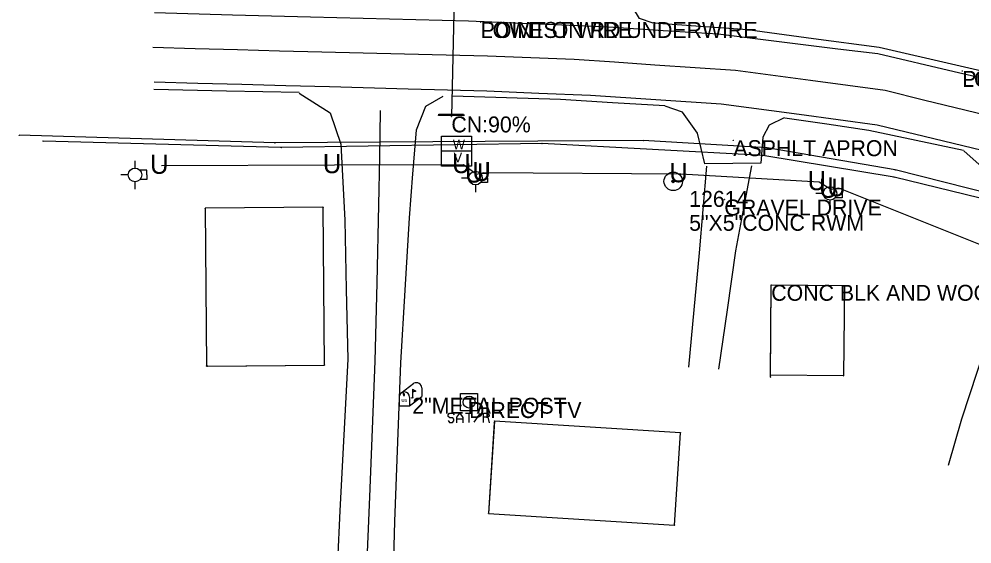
# Model space of a CAD drawing. Extents: x 1050807 to 1053552, y 395828 to 398415.
# Drawn here: x 1051514.4 to 1051813.5, y 397927.2 to 398091.9 of the extents above; entities that cross this region are included whole.
import ezdxf

# ---------------------------------------------------------------- set-up
doc = ezdxf.new("R2010")
doc.units = 0
for name, color, linetype in [('Default', 7, 'Continuous'), ('S_BUILDING', 7, 'Continuous'), ('S_BUILDING_ANNOT', 7, 'Continuous'), ('S_CROSS_DRAIN', 7, 'Continuous'), ('S_CROSS_DRAIN_ANNOT', 7, 'Continuous'), ('S_DRG_PT_SYM', 7, 'Continuous'), ('S_DRIVEWAY', 7, 'Continuous'), ('S_EDGE_PAVEMENT', 7, 'Continuous'), ('S_ELECTRIC_UTILITIES_ANNOT', 7, 'Continuous'), ('S_HEADWALL', 7, 'Continuous'), ('S_IRON_PIN', 7, 'Continuous'), ('S_IRON_PIN_ANNOT', 7, 'Continuous'), ('S_MAILBOX', 7, 'Continuous'), ('S_MAILBOX_ANNOT', 7, 'Continuous'), ('S_MSC_PT_SYM', 7, 'Continuous'), ('S_PAVEMENT_CROWN', 7, 'Continuous'), ('S_PHOTO_IRON_PIN', 7, 'Continuous'), ('S_SATELLITE_RECEIVER', 7, 'Continuous'), ('S_SATELLITE_RECEIVER_ANNOT', 7, 'Continuous'), ('S_SHOULDER', 7, 'Continuous'), ('S_STR_PT_SYM', 7, 'Continuous'), ('S_SURVEY_TEXT_ANNOT', 7, 'Continuous'), ('S_UNDERGROUND_CABLE', 7, 'Continuous'), ('S_UTILITY_POLE', 7, 'Continuous'), ('S_UTL_PT_SYM', 7, 'Continuous'), ('S_WATER_UTILITIES', 7, 'Continuous')]:
    doc.layers.add(name, color=color, linetype=linetype)

msp = doc.modelspace()

# ---------------------------------------------------------------- linework, layer by layer
at = {"layer": 'S_BUILDING'}
for p, q in [((1051609.83, 398032.84), (1051572.83, 398032.54)), ((1051572.83, 398032.54), (1051573.23, 397983.04)), ((1051610.23, 397983.34), (1051609.83, 398032.84)), ((1051750.22, 397979.55), (1051750.51, 398008.5)), ((1051750.22, 397980.2), (1051750.51, 398008.5)), ((1051750.51, 398008.5), (1051773.51, 398008.27)), ((1051773.51, 398008.27), (1051773.22, 397979.97)), ((1051573.23, 397983.04), (1051610.23, 397983.34)), ((1051573.61, 397983.04), (1051610.23, 397983.34)), ((1051773.22, 397979.97), (1051750.22, 397980.2)), ((1051663.58, 397965.75), (1051661.76, 397936.81)), ((1051663.55, 397965.29), (1051661.76, 397936.81)), ((1051721.97, 397962.09), (1051663.58, 397965.75)), ((1051720.15, 397933.14), (1051721.97, 397962.09)), ((1051661.76, 397936.81), (1051720.15, 397933.14))]:
    msp.add_line(p, q, dxfattribs=at)
at = {"layer": 'S_CROSS_DRAIN'}
msp.add_line((1051651.04, 398104.23), (1051650.09, 398061.31), dxfattribs=at)
at = {"layer": 'S_DRG_PT_SYM'}
msp.add_lwpolyline([(1051650.09, 398061.31), (1051650.09, 398061.36), (1051650.09, 398061.31), (1051650.04, 398061.31), (1051650.09, 398061.31), (1051650.09, 398061.26), (1051650.09, 398061.31), (1051650.14, 398061.31)], dxfattribs=at)
at = {"layer": 'S_DRIVEWAY'}
for points in [[(1051724.66, 397982.69), (1051726.32, 398000.62), (1051727.98, 398018.55), (1051729.11, 398032.13), (1051730.24, 398045.71)], [(1051744.33, 398045.87), (1051741.83, 398032.52), (1051739.33, 398019.18), (1051736.62, 398000.64), (1051733.9, 397982.1)], [(1051822.94, 398027.14), (1051824.81, 398010.97), (1051817.54, 397988.65), (1051810.28, 397966.32), (1051806.07, 397951.84)]]:
    msp.add_lwpolyline(points, dxfattribs=at)
at = {"layer": 'S_EDGE_PAVEMENT'}
for points in [[(1051713.48, 398090.6), (1051709.19, 398091.98), (1051705.31, 398098.47), (1051704.3, 398102.36), (1051704.31, 398113.47), (1051699.76, 398119.86), (1051701.99, 398138.89), (1051703.06, 398162.71)], [(1051831.93, 398069.76), (1051807.96, 398075.33), (1051783.99, 398080.9), (1051771.44, 398082.45), (1051758.89, 398083.99), (1051746.34, 398085.53), (1051733.79, 398087.07), (1051716.6, 398088.19), (1051699.41, 398089.32), (1051677.43, 398090.24), (1051655.45, 398091.16), (1051630.63, 398091.8), (1051605.81, 398092.43), (1051581.35, 398093.1), (1051556.88, 398093.77)], [(1051831.48, 398047.11), (1051807.63, 398052.86), (1051783.78, 398058.61), (1051759.29, 398061.91), (1051734.8, 398065.21), (1051714.29, 398066.53), (1051693.78, 398067.86), (1051677.51, 398068.56), (1051661.25, 398069.27), (1051636.55, 398069.92), (1051611.85, 398070.56), (1051598.08, 398070.93), (1051584.31, 398071.29), (1051570.54, 398071.66), (1051556.77, 398072.02)], [(1051602.35, 398068.65), (1051612.02, 398062.41), (1051615.42, 398052.6), (1051616.64, 398028.83), (1051617.09, 398007), (1051617.53, 397985.17), (1051616.73, 397969.32), (1051615.92, 397953.47), (1051615.11, 397937.61), (1051614.31, 397921.76), (1051613.72, 397908.61), (1051613.14, 397895.46), (1051612.55, 397882.3), (1051611.96, 397869.15), (1051612.02, 397847.38), (1051612.07, 397825.61), (1051611.81, 397807.62), (1051611.54, 397789.62)], [(1051647.36, 398067.62), (1051642.01, 398064.42), (1051639.06, 398057.05), (1051637.93, 398043.3), (1051636.8, 398029.54), (1051635.43, 398006.82), (1051634.07, 397984.09), (1051633.15, 397959.21), (1051632.23, 397934.32), (1051631.81, 397918.96), (1051631.38, 397903.6), (1051630.96, 397888.24), (1051630.54, 397872.88), (1051629.92, 397848.36), (1051629.3, 397823.83), (1051628.69, 397807.15), (1051628.08, 397790.46)], [(1051754.56, 398060.86), (1051749.82, 398058.53), (1051747.85, 398054.83), (1051747.28, 398046.63), (1051729.64, 398046.5), (1051727.32, 398056.1), (1051722.66, 398062.66), (1051717.25, 398064.51)], [(1051837.11, 398041.69), (1051834.35, 398039.68), (1051832.92, 398035.92), (1051829.91, 398026.23), (1051818.65, 398029.13), (1051819.81, 398036.54), (1051817.64, 398044.52), (1051811, 398050.54)]]:
    msp.add_lwpolyline(points, dxfattribs=at)
at = {"layer": 'S_HEADWALL'}
msp.add_lwpolyline([(1051653.95, 398061.96), (1051654.03, 398061.48), (1051646.07, 398061.59), (1051646.14, 398062.08), (1051653.87, 398062)], dxfattribs=at)
at = {"layer": 'S_IRON_PIN'}
for radius in [2.91, 0.411, 0.262, 0.212, 0.145, 0.0822, 0.0581]:
    msp.add_circle((1051719.74, 398040.95), radius, dxfattribs=at)
at = {"layer": 'S_MAILBOX'}
for p, q in [((1051634.21, 397974.51), (1051638.34, 397977.62)), ((1051637.83, 397975.8), (1051637.83, 397973.09)), ((1051640.78, 397976.15), (1051640.78, 397973.43)), ((1051633.66, 397973.24), (1051633.66, 397970.52)), ((1051636.98, 397970.52), (1051640.78, 397973.43)), ((1051636.98, 397973.24), (1051636.98, 397970.52)), ((1051633.66, 397970.52), (1051636.98, 397970.52))]:
    msp.add_line(p, q, dxfattribs=at)
for points in [[(1051634.84, 397974.35), (1051635.06, 397974.21), (1051635.06, 397973.83), (1051635.37, 397973.83), (1051635.37, 397974.19), (1051635.17, 397974.44), (1051634.84, 397974.38)], [(1051637.83, 397975.8), (1051638.93, 397975.14), (1051637.83, 397974.79)]]:
    msp.add_lwpolyline(points, dxfattribs=at)
for centre, end in [((1051639.11, 397976.15), 117.5718), ((1051635.32, 397973.24), 180)]:
    msp.add_arc(centre, 1.66, 0, end, dxfattribs=at)
msp.add_ellipse((1051637.83, 397973.09), major_axis=(0.145, 0.132), ratio=0.564646, dxfattribs=at)
at = {"layer": 'S_MSC_PT_SYM'}
for points in [[(1051659.3, 398090.93), (1051659.3, 398090.98), (1051659.3, 398090.93), (1051659.25, 398090.93), (1051659.3, 398090.93), (1051659.3, 398090.88), (1051659.3, 398090.93), (1051659.35, 398090.93)], [(1051810.46, 398075.58), (1051810.46, 398075.63), (1051810.46, 398075.58), (1051810.41, 398075.58), (1051810.46, 398075.58), (1051810.46, 398075.53), (1051810.46, 398075.58), (1051810.51, 398075.58)], [(1051738.6, 398053.86), (1051738.6, 398053.91), (1051738.6, 398053.86), (1051738.55, 398053.86), (1051738.6, 398053.86), (1051738.6, 398053.81), (1051738.6, 398053.86), (1051738.65, 398053.86)], [(1051735.78, 398035.25), (1051735.78, 398035.3), (1051735.78, 398035.25), (1051735.73, 398035.25), (1051735.78, 398035.25), (1051735.78, 398035.2), (1051735.78, 398035.25), (1051735.83, 398035.25)]]:
    msp.add_lwpolyline(points, dxfattribs=at)
at = {"layer": 'S_PAVEMENT_CROWN'}
for points in [[(1051823.74, 398060.25), (1051811.24, 398063.31), (1051798.75, 398066.36), (1051786.26, 398069.42), (1051762.78, 398072.58), (1051739.3, 398075.74), (1051726.62, 398076.59), (1051713.95, 398077.44), (1051701.28, 398078.29), (1051688.6, 398079.14), (1051675.02, 398079.7), (1051661.43, 398080.25), (1051648.42, 398080.55), (1051635.41, 398080.85), (1051622.4, 398081.15), (1051609.39, 398081.45), (1051596.15, 398081.82), (1051582.9, 398082.18), (1051569.66, 398082.54), (1051556.41, 398082.91)], [(1051619.24, 397791.01), (1051619.65, 397803.82), (1051620.06, 397816.63), (1051620.48, 397829.45), (1051620.89, 397842.26), (1051621.71, 397867.23), (1051622.53, 397892.19), (1051623.49, 397917.08), (1051624.46, 397941.96), (1051625.3, 397963.26), (1051626.14, 397984.55), (1051626.74, 398009.08), (1051627.35, 398033.62), (1051627.62, 398048.39), (1051627.88, 398063.17)]]:
    msp.add_lwpolyline(points, dxfattribs=at)
at = {"layer": 'S_PHOTO_IRON_PIN'}
msp.add_line((1051655.65, 397971.73), (1051655.65, 397971.73), dxfattribs=at)
at = {"layer": 'S_SATELLITE_RECEIVER'}
for p, q in [((1051649.04, 397967.75), (1051649.5, 397968.21)), ((1051649.04, 397967.2), (1051649.04, 397967.75)), ((1051649.58, 397966.82), (1051649.04, 397967.2)), ((1051649.04, 397965.96), (1051649.5, 397965.34)), ((1051649.5, 397968.21), (1051650.51, 397968.21)), ((1051649.5, 397965.34), (1051650.43, 397965.34)), ((1051650.51, 397966.82), (1051649.58, 397966.82)), ((1051650.43, 397965.34), (1051650.9, 397965.89)), ((1051650.51, 397968.21), (1051650.97, 397967.75)), ((1051650.9, 397966.35), (1051650.51, 397966.82)), ((1051650.9, 397965.89), (1051650.9, 397966.35)), ((1051651.75, 397966.97), (1051652.76, 397968.21)), ((1051651.75, 397965.19), (1051651.75, 397966.97)), ((1051653.61, 397966.35), (1051651.75, 397966.35)), ((1051652.76, 397968.21), (1051653.69, 397966.89)), ((1051653.69, 397966.89), (1051653.69, 397965.19)), ((1051654.54, 397968.21), (1051656.48, 397968.21)), ((1051655.55, 397968.21), (1051655.55, 397965.34)), ((1051657.25, 397965.42), (1051659.19, 397968.21)), ((1051660.2, 397965.34), (1051660.2, 397968.21)), ((1051660.2, 397968.21), (1051661.44, 397968.21)), ((1051661.51, 397966.97), (1051660.2, 397966.97)), ((1051661.44, 397968.21), (1051661.9, 397967.75)), ((1051661.9, 397967.36), (1051661.51, 397966.97)), ((1051661.51, 397966.97), (1051661.9, 397965.27)), ((1051661.9, 397967.75), (1051661.9, 397967.36))]:
    msp.add_line(p, q, dxfattribs=at)
msp.add_lwpolyline([(1051652.99, 397968.97), (1051652.99, 397974.47), (1051658.33, 397974.47), (1051658.33, 397968.97)], close=True, dxfattribs=at)
msp.add_circle((1051655.65, 397971.73), 1.86, dxfattribs=at)
at = {"layer": 'S_SHOULDER'}
for points in [[(1051832.54, 398071.82), (1051808.46, 398077.37), (1051784.37, 398082.92), (1051763.72, 398085.7), (1051743.06, 398088.49), (1051728.32, 398089.56), (1051713.58, 398090.62)], [(1051602.25, 398068.85), (1051579.46, 398069.29), (1051556.66, 398069.72)], [(1051717.05, 398064.59), (1051700.69, 398065.6), (1051684.32, 398066.61), (1051667.36, 398067.14), (1051650.4, 398067.68)], [(1051810.85, 398050.62), (1051795.99, 398053.77), (1051781.14, 398056.91), (1051767.94, 398058.86), (1051754.74, 398060.8)]]:
    msp.add_lwpolyline(points, dxfattribs=at)
at = {"layer": 'S_STR_PT_SYM'}
for points in [[(1051572.83, 398032.54), (1051572.83, 398032.59), (1051572.83, 398032.54), (1051572.78, 398032.54), (1051572.83, 398032.54), (1051572.83, 398032.49), (1051572.83, 398032.54), (1051572.88, 398032.54)], [(1051609.83, 398032.84), (1051609.83, 398032.89), (1051609.83, 398032.84), (1051609.78, 398032.84), (1051609.83, 398032.84), (1051609.83, 398032.79), (1051609.83, 398032.84), (1051609.88, 398032.84)], [(1051750.51, 398008.5), (1051750.51, 398008.55), (1051750.51, 398008.5), (1051750.46, 398008.5), (1051750.51, 398008.5), (1051750.51, 398008.45), (1051750.51, 398008.5), (1051750.56, 398008.5)], [(1051750.51, 398008.5), (1051750.51, 398008.55), (1051750.51, 398008.5), (1051750.46, 398008.5), (1051750.51, 398008.5), (1051750.51, 398008.45), (1051750.51, 398008.5), (1051750.56, 398008.5)], [(1051773.51, 398008.27), (1051773.51, 398008.32), (1051773.51, 398008.27), (1051773.46, 398008.27), (1051773.51, 398008.27), (1051773.51, 398008.22), (1051773.51, 398008.27), (1051773.56, 398008.27)], [(1051610.23, 397983.34), (1051610.23, 397983.39), (1051610.23, 397983.34), (1051610.18, 397983.34), (1051610.23, 397983.34), (1051610.23, 397983.29), (1051610.23, 397983.34), (1051610.28, 397983.34)], [(1051610.23, 397983.34), (1051610.23, 397983.39), (1051610.23, 397983.34), (1051610.18, 397983.34), (1051610.23, 397983.34), (1051610.23, 397983.29), (1051610.23, 397983.34), (1051610.28, 397983.34)], [(1051573.23, 397983.04), (1051573.23, 397983.09), (1051573.23, 397983.04), (1051573.18, 397983.04), (1051573.23, 397983.04), (1051573.23, 397982.99), (1051573.23, 397983.04), (1051573.28, 397983.04)], [(1051573.61, 397983.04), (1051573.61, 397983.09), (1051573.61, 397983.04), (1051573.56, 397983.04), (1051573.61, 397983.04), (1051573.61, 397982.99), (1051573.61, 397983.04), (1051573.66, 397983.04)], [(1051750.22, 397980.2), (1051750.22, 397980.25), (1051750.22, 397980.2), (1051750.17, 397980.2), (1051750.22, 397980.2), (1051750.22, 397980.15), (1051750.22, 397980.2), (1051750.27, 397980.2)], [(1051750.22, 397979.55), (1051750.22, 397979.6), (1051750.22, 397979.55), (1051750.17, 397979.55), (1051750.22, 397979.55), (1051750.22, 397979.5), (1051750.22, 397979.55), (1051750.27, 397979.55)], [(1051773.22, 397979.97), (1051773.22, 397980.02), (1051773.22, 397979.97), (1051773.17, 397979.97), (1051773.22, 397979.97), (1051773.22, 397979.92), (1051773.22, 397979.97), (1051773.27, 397979.97)], [(1051663.55, 397965.29), (1051663.55, 397965.34), (1051663.55, 397965.29), (1051663.5, 397965.29), (1051663.55, 397965.29), (1051663.55, 397965.24), (1051663.55, 397965.29), (1051663.6, 397965.29)], [(1051663.58, 397965.75), (1051663.58, 397965.8), (1051663.58, 397965.75), (1051663.53, 397965.75), (1051663.58, 397965.75), (1051663.58, 397965.7), (1051663.58, 397965.75), (1051663.63, 397965.75)], [(1051721.97, 397962.09), (1051721.97, 397962.14), (1051721.97, 397962.09), (1051721.92, 397962.09), (1051721.97, 397962.09), (1051721.97, 397962.04), (1051721.97, 397962.09), (1051722.02, 397962.09)], [(1051661.76, 397936.81), (1051661.76, 397936.86), (1051661.76, 397936.81), (1051661.71, 397936.81), (1051661.76, 397936.81), (1051661.76, 397936.76), (1051661.76, 397936.81), (1051661.81, 397936.81)], [(1051661.76, 397936.81), (1051661.76, 397936.86), (1051661.76, 397936.81), (1051661.71, 397936.81), (1051661.76, 397936.81), (1051661.76, 397936.76), (1051661.76, 397936.81), (1051661.81, 397936.81)], [(1051720.15, 397933.14), (1051720.15, 397933.19), (1051720.15, 397933.14), (1051720.1, 397933.14), (1051720.15, 397933.14), (1051720.15, 397933.09), (1051720.15, 397933.14), (1051720.2, 397933.14)]]:
    msp.add_lwpolyline(points, dxfattribs=at)
at = {"layer": 'S_UNDERGROUND_CABLE'}
for p, q in [((1051613.36, 398046.06), (1051559.12, 398045.86)), ((1051653.94, 398046.09), (1051613.36, 398046.06)), ((1051657.94, 398043.12), (1051653.94, 398046.09)), ((1051660.31, 398043.61), (1051657.94, 398043.12)), ((1051722.14, 398043.22), (1051660.31, 398043.61)), ((1051765.54, 398040.72), (1051722.14, 398043.22)), ((1051769.18, 398038.35), (1051765.54, 398040.72)), ((1051771.74, 398038.8), (1051769.18, 398038.35)), ((1051865.58, 398001.34), (1051771.74, 398038.8))]:
    msp.add_line(p, q, dxfattribs=at)
at = {"layer": 'S_UTILITY_POLE'}
for p, q in [((1051550.77, 398045.09), (1051550.77, 398047.34)), ((1051657.67, 398044.09), (1051657.67, 398046.34)), ((1051554.53, 398044.43), (1051552.32, 398044.43)), ((1051554.53, 398043), (1051554.53, 398044.43)), ((1051661.43, 398043.43), (1051659.22, 398043.43)), ((1051661.43, 398042), (1051661.43, 398043.43)), ((1051548.68, 398042.96), (1051546.35, 398042.96)), ((1051550.85, 398038.54), (1051550.85, 398040.87)), ((1051554.53, 398041.57), (1051552.32, 398041.57)), ((1051554.53, 398043), (1051554.53, 398041.57)), ((1051655.57, 398041.96), (1051653.25, 398041.96)), ((1051661.43, 398040.57), (1051659.22, 398040.57)), ((1051661.43, 398042), (1051661.43, 398040.57)), ((1051768.96, 398039.31), (1051768.96, 398041.56)), ((1051657.74, 398037.54), (1051657.74, 398039.87)), ((1051766.87, 398037.18), (1051764.55, 398037.18)), ((1051772.72, 398038.65), (1051770.51, 398038.65)), ((1051772.72, 398037.22), (1051772.72, 398038.65)), ((1051772.72, 398037.22), (1051772.72, 398035.79)), ((1051769.04, 398032.76), (1051769.04, 398035.09)), ((1051772.72, 398035.79), (1051770.51, 398035.79))]:
    msp.add_line(p, q, dxfattribs=at)
for centre in [(1051550.77, 398042.98), (1051657.67, 398041.98), (1051768.97, 398037.2)]:
    msp.add_circle(centre, 2.13, dxfattribs=at)
at = {"layer": 'S_UTL_PT_SYM'}
for points in [[(1051659.3, 398090.93), (1051659.3, 398090.98), (1051659.3, 398090.93), (1051659.25, 398090.93), (1051659.3, 398090.93), (1051659.3, 398090.88), (1051659.3, 398090.93), (1051659.35, 398090.93)], [(1051810.46, 398075.58), (1051810.46, 398075.63), (1051810.46, 398075.58), (1051810.41, 398075.58), (1051810.46, 398075.58), (1051810.46, 398075.53), (1051810.46, 398075.58), (1051810.51, 398075.58)], [(1051514.41, 398055.4), (1051514.41, 398055.45), (1051514.41, 398055.4), (1051514.36, 398055.4), (1051514.41, 398055.4), (1051514.41, 398055.35), (1051514.41, 398055.4), (1051514.46, 398055.4)], [(1051521.91, 398053.6), (1051521.91, 398053.65), (1051521.91, 398053.6), (1051521.86, 398053.6), (1051521.91, 398053.6), (1051521.91, 398053.55), (1051521.91, 398053.6), (1051521.96, 398053.6)], [(1051594.7, 398053), (1051594.7, 398053.05), (1051594.7, 398053), (1051594.65, 398053), (1051594.7, 398053), (1051594.7, 398052.95), (1051594.7, 398053), (1051594.75, 398053)], [(1051678.58, 398052.82), (1051678.58, 398052.87), (1051678.58, 398052.82), (1051678.53, 398052.82), (1051678.58, 398052.82), (1051678.58, 398052.77), (1051678.58, 398052.82), (1051678.63, 398052.82)], [(1051710.32, 398053.77), (1051710.32, 398053.82), (1051710.32, 398053.77), (1051710.27, 398053.77), (1051710.32, 398053.77), (1051710.32, 398053.72), (1051710.32, 398053.77), (1051710.37, 398053.77)], [(1051596.7, 398051.54), (1051596.7, 398051.59), (1051596.7, 398051.54), (1051596.65, 398051.54), (1051596.7, 398051.54), (1051596.7, 398051.49), (1051596.7, 398051.54), (1051596.75, 398051.54)], [(1051747.83, 398049.09), (1051747.83, 398049.14), (1051747.83, 398049.09), (1051747.78, 398049.09), (1051747.83, 398049.09), (1051747.83, 398049.04), (1051747.83, 398049.09), (1051747.88, 398049.09)], [(1051749.21, 398051.47), (1051749.21, 398051.52), (1051749.21, 398051.47), (1051749.16, 398051.47), (1051749.21, 398051.47), (1051749.21, 398051.42), (1051749.21, 398051.47), (1051749.26, 398051.47)], [(1051789.46, 398044.53), (1051789.46, 398044.58), (1051789.46, 398044.53), (1051789.41, 398044.53), (1051789.46, 398044.53), (1051789.46, 398044.48), (1051789.46, 398044.53), (1051789.51, 398044.53)], [(1051789.07, 398042.3), (1051789.07, 398042.35), (1051789.07, 398042.3), (1051789.02, 398042.3), (1051789.07, 398042.3), (1051789.07, 398042.25), (1051789.07, 398042.3), (1051789.12, 398042.3)]]:
    msp.add_lwpolyline(points, dxfattribs=at)
at = {"layer": 'S_WATER_UTILITIES'}
for p, q in [((1051594.7, 398053), (1051514.41, 398055.4)), ((1051647.01, 398055.17), (1051656.43, 398055.17)), ((1051647.01, 398045.75), (1051647.01, 398055.17)), ((1051656.43, 398055.17), (1051656.43, 398045.75)), ((1051596.7, 398051.54), (1051521.91, 398053.6)), ((1051710.32, 398053.77), (1051594.7, 398053)), ((1051678.58, 398052.82), (1051596.7, 398051.54)), ((1051747.83, 398049.09), (1051678.58, 398052.82)), ((1051749.21, 398051.47), (1051710.32, 398053.77)), ((1051647.01, 398050.48), (1051656.43, 398050.48)), ((1051789.07, 398042.3), (1051747.83, 398049.09)), ((1051789.46, 398044.53), (1051749.21, 398051.47)), ((1051656.43, 398045.75), (1051647.01, 398045.75)), ((1051834.35, 398033.24), (1051789.46, 398044.53)), ((1051833.2, 398031.46), (1051789.07, 398042.3))]:
    msp.add_line(p, q, dxfattribs=at)

# ---------------------------------------------------------------- texts
at = {"layer": 'Default'}
for p in [(1051555.49, 398043.32), (1051609.73, 398043.51), (1051650.31, 398043.54), (1051654.32, 398040.57), (1051656.68, 398041.07), (1051718.51, 398040.67), (1051761.91, 398038.18), (1051765.55, 398035.81), (1051768.11, 398036.25)]:
    msp.add_text('U', height=6, dxfattribs=at).set_placement(p)
at = {"layer": 'S_BUILDING_ANNOT'}
msp.add_text('CONC BLK AND WOOD BLDG TA', height=5, dxfattribs=at).set_placement((1051750.51, 398003.5))
at = {"layer": 'S_CROSS_DRAIN_ANNOT'}
msp.add_text('CN:90%', height=5, dxfattribs=at).set_placement((1051650.09, 398056.31))
at = {"layer": 'S_ELECTRIC_UTILITIES_ANNOT'}
for p in [(1051659.3, 398085.93), (1051810.46, 398070.58)]:
    msp.add_text('LOWEST WIRE', height=5, dxfattribs=at).set_placement(p)
at = {"layer": 'S_IRON_PIN_ANNOT'}
for s, p in [('12614', (1051724.74, 398032.95)), ('5"X5"CONC RWM', (1051724.74, 398025.45))]:
    msp.add_text(s, height=5, dxfattribs=at).set_placement(p)
at = {"layer": 'S_MAILBOX'}
msp.add_text('US', height=0.96, dxfattribs=at).set_placement((1051634.42, 397971.72))
at = {"layer": 'S_MAILBOX_ANNOT'}
msp.add_text('2"METAL POST', height=5, dxfattribs=at).set_placement((1051637.83, 397968.09))
at = {"layer": 'S_SATELLITE_RECEIVER_ANNOT'}
msp.add_text('DIRECT TV', height=5, dxfattribs=at).set_placement((1051655.65, 397966.73))
at = {"layer": 'S_SURVEY_TEXT_ANNOT'}
for s, p in [('POINT ON RD UNDERWIRE', (1051659.3, 398085.93)), ('POINT ON RD UNDERWIRE', (1051810.46, 398070.58)), ('ASPHLT APRON', (1051738.6, 398048.86)), ('GRAVEL DRIVE', (1051735.78, 398030.25))]:
    msp.add_text(s, height=5, dxfattribs=at).set_placement(p)
at = {"layer": 'S_WATER_UTILITIES'}
for s, p in [('W', (1051650.56, 398051.01)), ('V', (1051650.8, 398046.95))]:
    msp.add_text(s, height=3, dxfattribs=at).set_placement(p)

doc.saveas('drawing.dxf')
